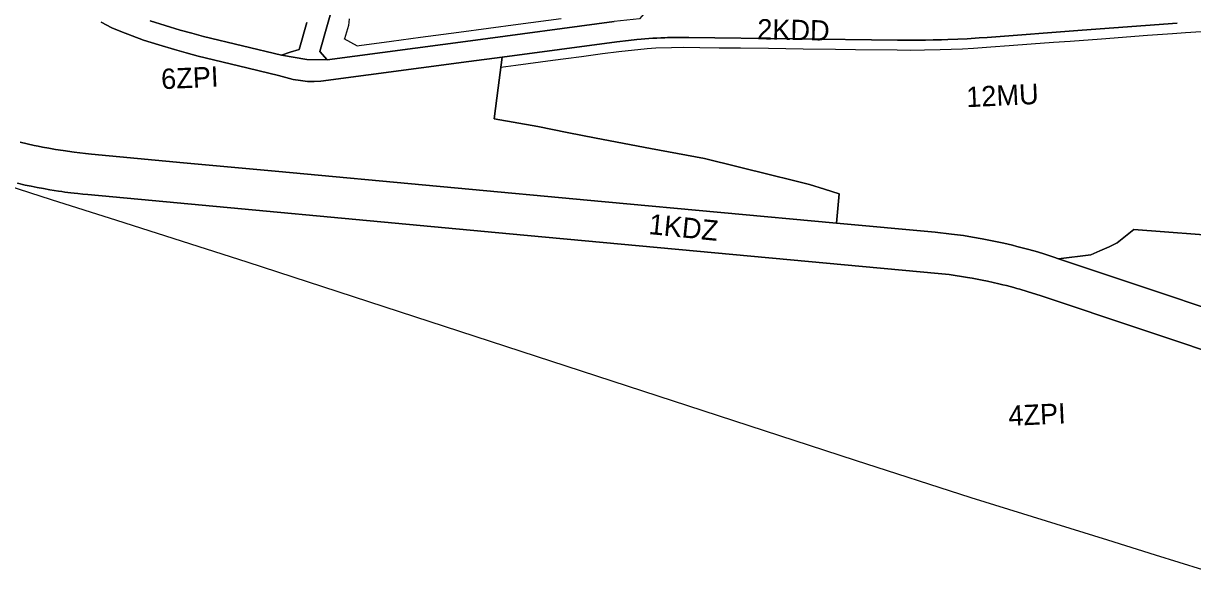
# Model space of a CAD drawing. Extents: x 7418021 to 7419743, y 5540231 to 5541685.
# Drawn here: x 7418764 to 7419340, y 5540238 to 5540509 of the extents above; entities that cross this region are included whole.
import ezdxf

# ---------------------------------------------------------------- set-up
doc = ezdxf.new("R2010")
doc.units = 0
for name, color, linetype in [('linie_rozgraniczajace', 7, 'Continuous'), ('linie_zabudowy_nieprzekraczalne', 7, 'Continuous'), ('oznaczenia_przeznaczen', 7, 'Continuous')]:
    doc.layers.add(name, color=color, linetype=linetype)

msp = doc.modelspace()

# ---------------------------------------------------------------- linework, layer by layer
at = {"layer": 'linie_rozgraniczajace'}
for points in [[(7418938.17, 5540602.64), (7418963.79, 5540604.94), (7418989.41, 5540607.25), (7419027.14, 5540603.92), (7419064.86, 5540600.6), (7419066.58, 5540580.83), (7419072.18, 5540516.17), (7419067.63, 5540510.82), (7419055.07, 5540509.46), (7418984.43, 5540500.04), (7418913.79, 5540490.61), (7418910.2, 5540494.76), (7418921.59, 5540534.82), (7418932.97, 5540574.89), (7418935.14, 5540583.49), (7418936.07, 5540587.9), (7418936.64, 5540591.04), (7418937.19, 5540594.46), (7418937.41, 5540596.09), (7418937.82, 5540599.28), (7418938, 5540600.85)], [(7419273.82, 5540392.82), (7419289.73, 5540394.72), (7419294.26, 5540396.72), (7419298.78, 5540398.73), (7419302.65, 5540400.69), (7419306.78, 5540403.98), (7419310.92, 5540407.28), (7419358.35, 5540403.61), (7419405.78, 5540399.94), (7419387.79, 5540365.27), (7419380.68, 5540362.41), (7419373.53, 5540359.49), (7419322.56, 5540376.53)]]:
    msp.add_lwpolyline(points, close=True, dxfattribs=at)
for points in [[(7418921.59, 5540534.82), (7418910.2, 5540494.76), (7418913.79, 5540490.61), (7418903.9, 5540490.83), (7418891.42, 5540493.01), (7418895.7, 5540494.41), (7418899.99, 5540495.81), (7418903.76, 5540509)], [(7418802.54, 5540509.18), (7418807.88, 5540506.48), (7418812.27, 5540504.66), (7418817.86, 5540502.55), (7418823.44, 5540500.43), (7418831.04, 5540498.08), (7418838.63, 5540495.72), (7418844.52, 5540494.11), (7418850.4, 5540492.5), (7418870.13, 5540487.72), (7418889.85, 5540482.95), (7418893.49, 5540481.95), (7418897.13, 5540480.95), (7418900.68, 5540480.44), (7418904.24, 5540479.94), (7418907.53, 5540480.03), (7418910.81, 5540480.12), (7418983.6, 5540489.84), (7418999.94, 5540492.02), (7418997.98, 5540476.86), (7418996.03, 5540461.71), (7419017.48, 5540457.86), (7419031.91, 5540455), (7419046.34, 5540452.14), (7419072.95, 5540447.11), (7419099.56, 5540442.08), (7419116.14, 5540438.03), (7419132.71, 5540433.98), (7419142.04, 5540431.7), (7419151.36, 5540429.42), (7419158.65, 5540427.05), (7419165.95, 5540424.68), (7419165.18, 5540417.53), (7419164.53, 5540410.36), (7419050.69, 5540420.89), (7418888.28, 5540435.9), (7418843.07, 5540440.08), (7418797.86, 5540444.26), (7418794.96, 5540444.55), (7418789.23, 5540445.22), (7418783.85, 5540446), (7418780.06, 5540446.58), (7418776.88, 5540447.16), (7418773.7, 5540447.74), (7418771.63, 5540448.17), (7418769.57, 5540448.59), (7418766.16, 5540449.38), (7418762.74, 5540450.16)], [(7419332.34, 5540508.71), (7419285.51, 5540505.21), (7419238.69, 5540501.72), (7419234.79, 5540501.44), (7419228.87, 5540501.08), (7419224.25, 5540500.85), (7419219.38, 5540500.65), (7419216.19, 5540500.54), (7419212.1, 5540500.44), (7419208.34, 5540500.37), (7419205.4, 5540500.34), (7419202.33, 5540500.33), (7419199.27, 5540500.32), (7419196.93, 5540500.34), (7419194.6, 5540500.36), (7419143.28, 5540501.02), (7419091.96, 5540501.69), (7419088.59, 5540501.71), (7419087.04, 5540501.69), (7419085.48, 5540501.68), (7419084.17, 5540501.66), (7419082.86, 5540501.63), (7419081.43, 5540501.59), (7419079.99, 5540501.55), (7419078.03, 5540501.46), (7419076.06, 5540501.37), (7419074.09, 5540501.26), (7419072.13, 5540501.14), (7419070.25, 5540501), (7419068.37, 5540500.85), (7419066.21, 5540500.65), (7419062.16, 5540500.25), (7419056.39, 5540499.55), (7418999.94, 5540492.02), (7418983.6, 5540489.84), (7418910.81, 5540480.12), (7418907.53, 5540480.03), (7418904.24, 5540479.94), (7418900.68, 5540480.44), (7418897.13, 5540480.95), (7418893.49, 5540481.95), (7418889.85, 5540482.95), (7418870.13, 5540487.72), (7418850.4, 5540492.5), (7418844.52, 5540494.11), (7418838.63, 5540495.72), (7418831.04, 5540498.08), (7418823.44, 5540500.43), (7418817.86, 5540502.55), (7418812.27, 5540504.66), (7418807.88, 5540506.48), (7418802.54, 5540509.18)], [(7418826.7, 5540509.9), (7418834.07, 5540507.61), (7418841.44, 5540505.32), (7418847.17, 5540503.75), (7418852.9, 5540502.18), (7418872.16, 5540497.6), (7418891.42, 5540493.01), (7418903.9, 5540490.83), (7418913.79, 5540490.61), (7418984.43, 5540500.04), (7419055.07, 5540509.46)], [(7418903.76, 5540509), (7418899.99, 5540495.81), (7418895.7, 5540494.41), (7418891.42, 5540493.01), (7418872.16, 5540497.6), (7418852.9, 5540502.18), (7418847.17, 5540503.75), (7418841.44, 5540505.32), (7418834.07, 5540507.61), (7418826.7, 5540509.9)], [(7419358.35, 5540403.61), (7419310.92, 5540407.28), (7419306.78, 5540403.98), (7419302.65, 5540400.69), (7419298.78, 5540398.73), (7419294.26, 5540396.72), (7419289.73, 5540394.72), (7419273.82, 5540392.82), (7419271.59, 5540393.57), (7419266.06, 5540395.34), (7419262.29, 5540396.48), (7419258, 5540397.69), (7419253.35, 5540398.92), (7419251.15, 5540399.48), (7419246.92, 5540400.48), (7419241.28, 5540401.69), (7419236.28, 5540402.66), (7419231.48, 5540403.5), (7419227.03, 5540404.19), (7419221.2, 5540404.97), (7419213.1, 5540405.87), (7419164.53, 5540410.36), (7419165.18, 5540417.53), (7419165.95, 5540424.68), (7419158.65, 5540427.05), (7419151.36, 5540429.42), (7419142.04, 5540431.7), (7419132.71, 5540433.98), (7419116.14, 5540438.03), (7419099.56, 5540442.08), (7419072.95, 5540447.11), (7419046.34, 5540452.14), (7419031.91, 5540455), (7419017.48, 5540457.86), (7418996.03, 5540461.71), (7418997.98, 5540476.86), (7418999.94, 5540492.02), (7419056.39, 5540499.55), (7419062.16, 5540500.25), (7419066.21, 5540500.65), (7419068.37, 5540500.85), (7419070.25, 5540501), (7419072.13, 5540501.14), (7419074.09, 5540501.26), (7419076.06, 5540501.37), (7419078.03, 5540501.46), (7419079.99, 5540501.55), (7419081.43, 5540501.59), (7419082.86, 5540501.63), (7419084.17, 5540501.66), (7419085.48, 5540501.68), (7419087.04, 5540501.69), (7419088.59, 5540501.71), (7419091.96, 5540501.69), (7419143.28, 5540501.02), (7419194.6, 5540500.36), (7419196.93, 5540500.34), (7419199.27, 5540500.32), (7419202.33, 5540500.33), (7419205.4, 5540500.34), (7419208.34, 5540500.37), (7419212.1, 5540500.44), (7419216.19, 5540500.54), (7419219.38, 5540500.65), (7419224.25, 5540500.85), (7419228.87, 5540501.08), (7419234.79, 5540501.44), (7419238.69, 5540501.72), (7419285.51, 5540505.21), (7419332.34, 5540508.71)], [(7418762.74, 5540450.16), (7418766.16, 5540449.38), (7418769.57, 5540448.59), (7418771.63, 5540448.17), (7418773.7, 5540447.74), (7418776.88, 5540447.16), (7418780.06, 5540446.58), (7418783.85, 5540446), (7418789.23, 5540445.22), (7418794.96, 5540444.55), (7418797.86, 5540444.26), (7418843.07, 5540440.08), (7418888.28, 5540435.9), (7419050.69, 5540420.89), (7419164.53, 5540410.36), (7419213.1, 5540405.87), (7419221.2, 5540404.97), (7419227.03, 5540404.19), (7419231.48, 5540403.5), (7419236.28, 5540402.66), (7419241.28, 5540401.69), (7419246.92, 5540400.48), (7419251.15, 5540399.48), (7419253.35, 5540398.92), (7419258, 5540397.69), (7419262.29, 5540396.48), (7419266.06, 5540395.34), (7419271.59, 5540393.57), (7419273.82, 5540392.82), (7419322.56, 5540376.53), (7419373.53, 5540359.49)], [(7419173.94, 5540293.61), (7418874.42, 5540391.1), (7418810.36, 5540411.56), (7418778.14, 5540421.84), (7418745.92, 5540432.13)], [(7419364.45, 5540341.44), (7419314.85, 5540358.02), (7419265.25, 5540374.6), (7419258.41, 5540376.77), (7419254.8, 5540377.83), (7419253.31, 5540378.24), (7419251.81, 5540378.66), (7419250.01, 5540379.13), (7419248.21, 5540379.6), (7419246.37, 5540380.05), (7419244.52, 5540380.51), (7419241.72, 5540381.13), (7419238.93, 5540381.76), (7419236.35, 5540382.28), (7419233.78, 5540382.8), (7419231.4, 5540383.22), (7419229.03, 5540383.64), (7419226.03, 5540384.11), (7419223.02, 5540384.58), (7419220.02, 5540385.04), (7419214.62, 5540385.62), (7419003.64, 5540405.15), (7418796.02, 5540424.35), (7418793.55, 5540424.6), (7418791.09, 5540424.85), (7418789.38, 5540425.05), (7418787.68, 5540425.25), (7418784.69, 5540425.65), (7418783.17, 5540425.86), (7418781.66, 5540426.08), (7418779.5, 5540426.42), (7418777.33, 5540426.76), (7418774.21, 5540427.32), (7418771.09, 5540427.87), (7418768.15, 5540428.47), (7418765.21, 5540429.07), (7418761.34, 5540429.97)], [(7418761.34, 5540429.97), (7418765.21, 5540429.07), (7418768.15, 5540428.47), (7418771.09, 5540427.87), (7418774.21, 5540427.32), (7418777.33, 5540426.76), (7418779.5, 5540426.42), (7418781.66, 5540426.08), (7418783.17, 5540425.86), (7418784.69, 5540425.65), (7418787.68, 5540425.25), (7418789.38, 5540425.05), (7418791.09, 5540424.85), (7418793.55, 5540424.6), (7418796.02, 5540424.35), (7419003.64, 5540405.15), (7419214.62, 5540385.62), (7419220.02, 5540385.04), (7419223.02, 5540384.58), (7419226.03, 5540384.11), (7419229.03, 5540383.64), (7419231.4, 5540383.22), (7419233.78, 5540382.8), (7419236.35, 5540382.28), (7419238.93, 5540381.76), (7419241.72, 5540381.13), (7419244.52, 5540380.51), (7419246.37, 5540380.05), (7419248.21, 5540379.6), (7419250.01, 5540379.13), (7419251.81, 5540378.66), (7419253.31, 5540378.24), (7419254.8, 5540377.83), (7419258.41, 5540376.77), (7419265.25, 5540374.6), (7419314.85, 5540358.02), (7419364.45, 5540341.44)], [(7419352.41, 5540267.94), (7419351.85, 5540263.93), (7419351.28, 5540259.93), (7419350.84, 5540255.88), (7419350.4, 5540251.84), (7419350.08, 5540247.8), (7419349.77, 5540243.77), (7419349.62, 5540241.08), (7419349.47, 5540238.4), (7419344.96, 5540239.8), (7419321.54, 5540247.04), (7419298.12, 5540254.28), (7419230.79, 5540275.11), (7419173.94, 5540293.61)]]:
    msp.add_lwpolyline(points, dxfattribs=at)
at = {"layer": 'linie_zabudowy_nieprzekraczalne'}
for points in [[(7418924.37, 5540507.64), (7418922.38, 5540501.08)], [(7418924.75, 5540510.77), (7418924.37, 5540507.64)], [(7418978.67, 5540504.31), (7419007.86, 5540508.21)], [(7419007.86, 5540508.21), (7419029.1, 5540511.04)], [(7418945.48, 5540499.88), (7418959.82, 5540501.8)], [(7418959.82, 5540501.8), (7418978.67, 5540504.31)], [(7419317.65, 5540502.6), (7419294.96, 5540500.91)], [(7419330.03, 5540503.52), (7419317.65, 5540502.6)], [(7419336.43, 5540503.95), (7419330.03, 5540503.52)], [(7419354.41, 5540505.04), (7419336.43, 5540503.95)], [(7418922.09, 5540501.2), (7418928.64, 5540497.64)], [(7418928.64, 5540497.64), (7418929.52, 5540497.75)], [(7418929.52, 5540497.75), (7418945.48, 5540499.88)], [(7419071.43, 5540496.07), (7419057.37, 5540494.64)], [(7419075.63, 5540496.34), (7419071.43, 5540496.07)], [(7419083.33, 5540496.64), (7419075.63, 5540496.34)], [(7419089.31, 5540496.71), (7419083.33, 5540496.64)], [(7419097.37, 5540496.62), (7419089.31, 5540496.71)], [(7419106.83, 5540496.5), (7419097.37, 5540496.62)], [(7419117.3, 5540496.36), (7419106.83, 5540496.5)], [(7419131.03, 5540496.18), (7419117.3, 5540496.36)], [(7419148.09, 5540495.96), (7419131.03, 5540496.18)], [(7419231.99, 5540496.26), (7419226.58, 5540495.96)], [(7419236.34, 5540496.54), (7419231.99, 5540496.26)], [(7419240.51, 5540496.84), (7419236.34, 5540496.54)], [(7419249.57, 5540497.52), (7419240.51, 5540496.84)], [(7419260.38, 5540498.32), (7419249.57, 5540497.52)], [(7419271.38, 5540499.15), (7419260.38, 5540498.32)], [(7419279.61, 5540499.76), (7419271.38, 5540499.15)], [(7419294.96, 5540500.91), (7419279.61, 5540499.76)], [(7419024.94, 5540490.31), (7419006.72, 5540487.88)], [(7419031.34, 5540491.17), (7419024.94, 5540490.31)], [(7419038.98, 5540492.19), (7419031.34, 5540491.17)], [(7419049.37, 5540493.57), (7419038.98, 5540492.19)], [(7419057.37, 5540494.64), (7419049.37, 5540493.57)], [(7419164.06, 5540495.76), (7419148.09, 5540495.96)], [(7419174, 5540495.63), (7419164.06, 5540495.76)], [(7419194.47, 5540495.36), (7419174, 5540495.63)], [(7419201.09, 5540495.33), (7419194.47, 5540495.36)], [(7419207.9, 5540495.37), (7419201.09, 5540495.33)], [(7419215.58, 5540495.53), (7419207.9, 5540495.37)], [(7419220.99, 5540495.71), (7419215.58, 5540495.53)], [(7419226.58, 5540495.96), (7419220.99, 5540495.71)], [(7419006.72, 5540487.88), (7418999.28, 5540486.89)]]:
    msp.add_lwpolyline(points, dxfattribs=at)

# ---------------------------------------------------------------- texts
at = {"layer": 'oznaczenia_przeznaczen'}
for s, rotation, p in [('2KDD', 358.88788, (7419125.46, 5540500.77)), ('6ZPI', 2.66896, (7418832.33, 5540476.2)), ('12MU', 2.66896, (7419228.66, 5540467.35)), ('1KDZ', 354.24112, (7419071.82, 5540405)), ('4ZPI', 2.66896, (7419249.39, 5540310.53))]:
    msp.add_text(s, height=10, rotation=rotation, dxfattribs=at).set_placement(p)

doc.saveas('drawing.dxf')
